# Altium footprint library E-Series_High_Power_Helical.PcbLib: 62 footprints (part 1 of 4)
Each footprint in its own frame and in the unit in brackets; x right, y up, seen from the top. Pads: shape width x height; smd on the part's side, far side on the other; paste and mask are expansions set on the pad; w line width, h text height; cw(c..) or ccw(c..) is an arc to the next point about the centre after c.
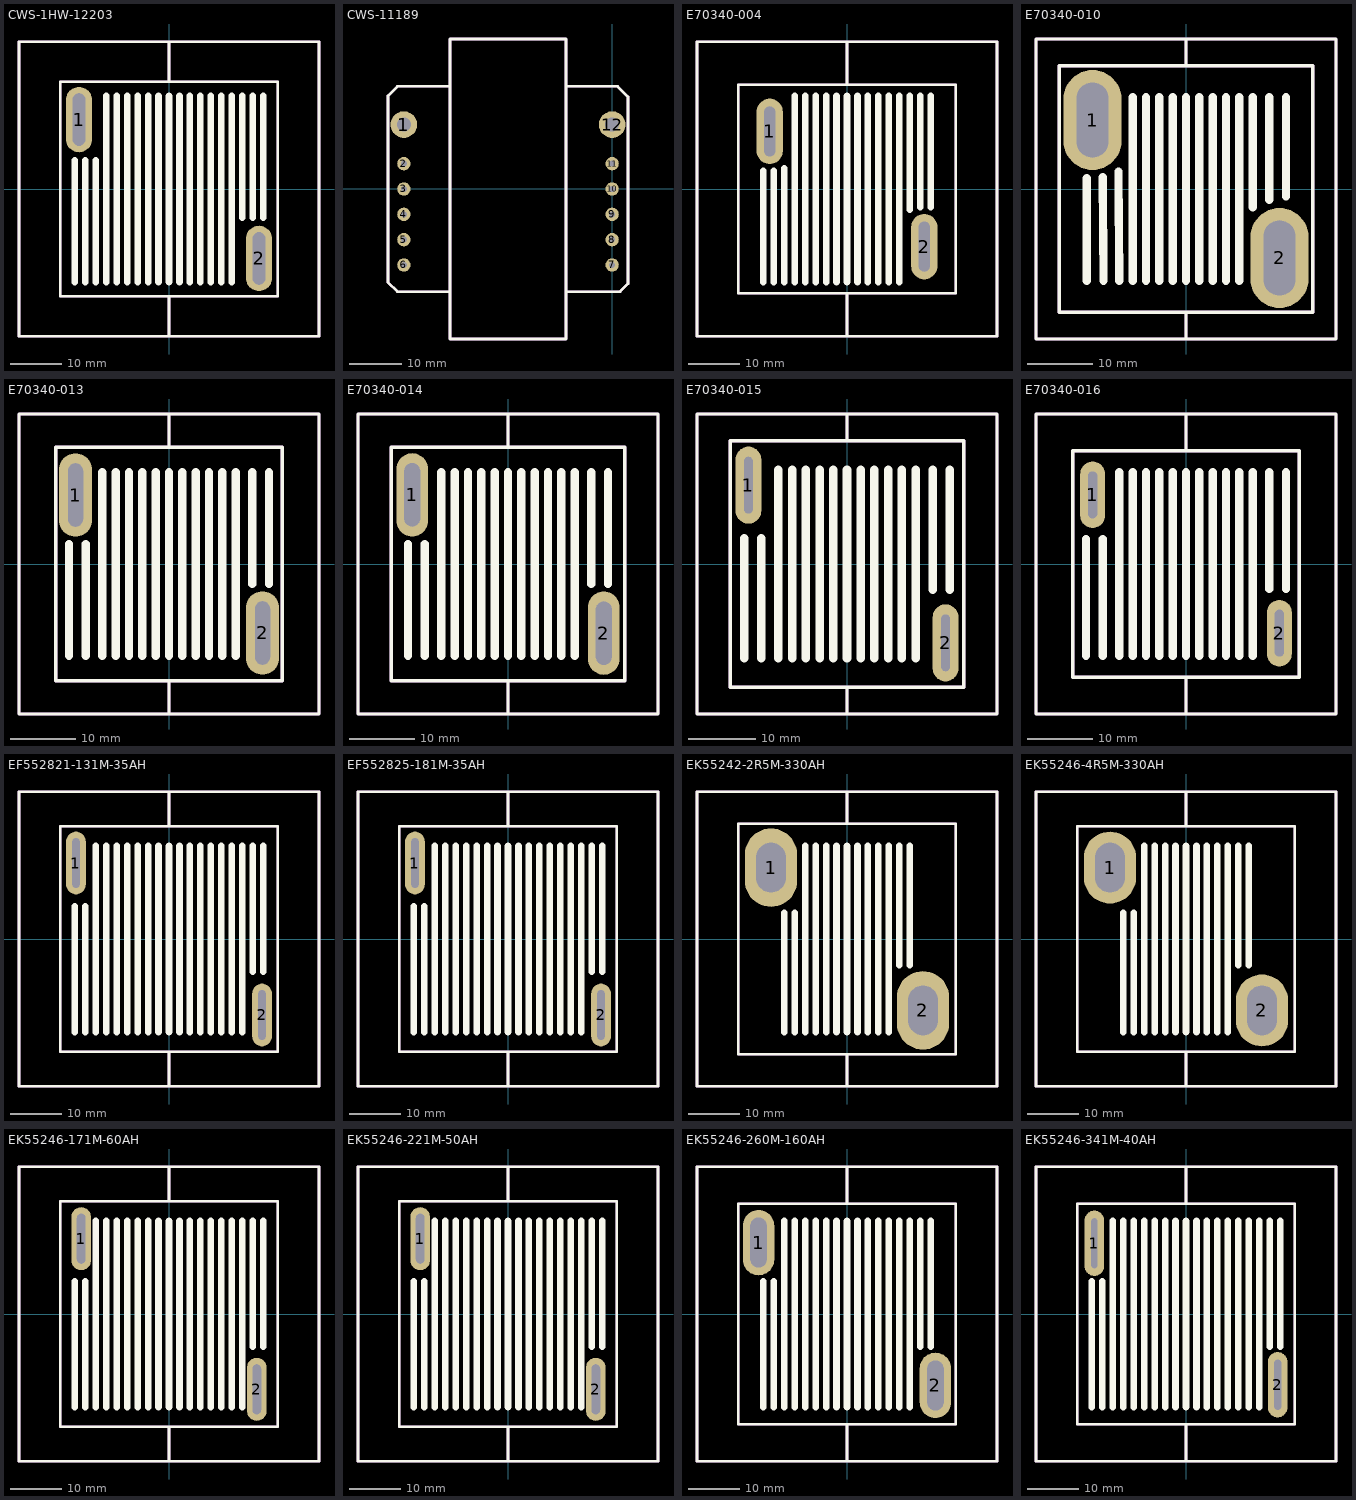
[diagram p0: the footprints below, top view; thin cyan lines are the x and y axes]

## CWS-1HW-12203 [mil]
pads (2):
  oval 200x500 hole 95 slot 400 at 90 deg: 1(-687,530) 2(687,-530)
Top Overlay:
  lines w19.68: 0,-1120 0,-820 ; 0,820 0,1120 ; -1145,-1125 -1145,1125 1145,1125 1145,-1125 -1145,-1125 ; -830,-820 -830,820 830,820 830,-820 -830,-820
  lines w50: -720,-710 -720,220 ; -640,-710 -640,220 ; -560,-710 -560,220 ; -480,-710 -480,710 ; -400,-710 -400,710 ; -320,-710 -320,710 ; -240,-710 -240,710 ; -160,-710 -160,710 ; -80,-710 -80,710 ; 0,-710 0,710 ; 80,-710 80,710 ; 160,-710 160,710 ; 240,-710 240,710 ; 320,-710 320,710 ; 400,-710 400,710 ; 480,-710 480,710 ; 560,-220 560,710 ; 640,-220 640,710 ; 720,-220 720,710
Components Top Assy:
  lines w19.68: 0,-1120 0,-820 ; 0,820 0,1120 ; -1145,-1125 -1145,1125 1145,1125 1145,-1125 -1145,-1125 ; -830,-820 -830,820 830,820 830,-820 -830,-820
  text "'.Designator'" at -938.15,-44.83 h400

## CWS-11189 [mil]
pads (12):
  round 200 hole 105: 1(-1562,483) 12(0,483)
  round 100 hole 45: 2(-1562,190) 3(-1562,0) 4(-1562,-190) 5(-1562,-380) 6(-1562,-570) 7(0,-570) 8(0,-380) 9(0,-190) 10(0,0) 11(0,190)
Top Overlay:
  lines w19.68: -1220,-770 -1607.04,-770 -1611.2,-770 -1681,-700.2 -1681,-690 -1681,669.63 -1681,699 -1610,770 -1580.42,770 -1220,770 ; -1216,1120 -1216,-1125 -346,-1125 -346,1120 ; -1216,1125 -346,1125 ; -340,-770 58.58,-770 119,-709.58 119,691 40,770 -340,770
Components Top Assy:
  lines w19.68: -1220,-770 -1607.04,-770 -1611.2,-770 -1681,-700.2 -1681,-690 -1681,669.63 -1681,699 -1610,770 -1580.42,770 -1220,770 ; -1216,1120 -1216,-1125 -346,-1125 -346,1120 ; -1216,1125 -346,1125 ; -340,-770 58.58,-770 119,-709.58 119,691 40,770 -340,770
  text "'.Designator'" at -1750,-64.83 h400

## E70340-004 [mil]
pads (2):
  oval 200x500 hole 85 slot 380 at 90 deg: 1(-590,440) 2(590,-440)
Top Overlay:
  lines w19.68: 0,-1120 0,-795 ; 0,800 0,1120 ; -1145,-1125 -1145,1125 1145,1125 1145,-1125 -1145,-1125 ; -830,-795 -830,795 830,795 830,-795 -830,-795
  lines w50: -640,-710 -640,140 ; -560,-710 -560,140 ; -480,-710 -480,160 ; -400,-710 -400,710 ; -320,-710 -320,710 ; -240,-710 -240,710 ; -160,-710 -160,710 ; -80,-710 -80,710 ; 0,-710 0,710 ; 80,-710 80,710 ; 160,-710 160,710 ; 240,-710 240,710 ; 320,-710 320,710 ; 400,-710 400,710 ; 480,-160 480,710 ; 560,-140 560,710 ; 640,-140 640,710
Components Top Assy:
  lines w19.68: 0,-1120 0,-795 ; 0,800 0,1120 ; -1145,-1125 -1145,1125 1145,1125 1145,-1125 -1145,-1125 ; -830,-795 -830,795 830,795 830,-795 -830,-795
  text "'.Designator'" at -938.15,-44.83 h400

## E70340-010 [mil]
pads (2):
  oval 350x600 hole 190 slot 450 at 90 deg: 1(-561,414) 2(561,-414)
Top Overlay:
  lines w19.68: 0,-890 0,-740 ; 0,740 0,895 ; -900,-900 900,-900 900,900 -900,900 -900,-900 ; -760,-740 760,-740 760,740 -760,740 -760,-740
  lines w50: -595,-550 -595,65 ; -500,70 -495,-550 ; -405,105 -400,-550 ; -320,-550 -320,550 ; -240,-550 -240,550 ; -160,-550 -160,550 ; -80,-550 -80,550 ; 0,-550 0,550 ; 80,-550 80,550 ; 160,-550 160,550 ; 240,-550 240,550 ; 320,-550 320,550 ; 400,-110 400,550 ; 500,-65 500,550 ; 600,-45 600,550
Components Top Assy:
  lines w19.68: 0,-890 0,-740 ; 0,740 0,895 ; -900,-900 900,-900 900,900 -900,900 -900,-900 ; -760,-740 760,-740 760,740 -760,740 -760,-740
  text "'.Designator'" at -928.15,-44.83 h400

## E70340-013 [mil]
pads (2):
  oval 200x500 hole 90 slot 380 at 90 deg: 1(-561,414) 2(561,-414)
Top Overlay:
  lines w19.68: 0,-890 0,-700 ; 0,700 0,895 ; -900,-900 -900,900 900,900 900,-900 -900,-900 ; -680,-700 -680,700 680,700 680,-700 -680,-700
  lines w50: -600,-550 -600,120 ; -500,-550 -500,120 ; -400,-550 -400,550 ; -320,-550 -320,550 ; -240,-550 -240,550 ; -160,-550 -160,550 ; -80,-550 -80,550 ; 0,-550 0,550 ; 80,-550 80,550 ; 160,-550 160,550 ; 240,-550 240,550 ; 320,-550 320,550 ; 400,-550 400,550 ; 500,-120 500,550 ; 600,-120 600,550
Components Top Assy:
  lines w19.68: 0,-890 0,-700 ; 0,700 0,895 ; -900,-900 -900,900 900,900 900,-900 -900,-900 ; -680,-700 -680,700 680,700 680,-700 -680,-700
  text "'.Designator'" at -928.15,-44.83 h400

## E70340-014 [mil]
pads (2):
  oval 190x500 hole 95 slot 380 at 90 deg: 1(-575,415) 2(575,-415)
Top Overlay:
  lines w19.68: 0,-890 0,-700 ; 0,700 0,895 ; -900,-900 -900,900 900,900 900,-900 -900,-900 ; -700,-700 -700,700 700,700 700,-700 -700,-700
  lines w50: -600,-550 -600,120 ; -500,-550 -500,120 ; -400,-550 -400,550 ; -320,-550 -320,550 ; -240,-550 -240,550 ; -160,-550 -160,550 ; -80,-550 -80,550 ; 0,-550 0,550 ; 80,-550 80,550 ; 160,-550 160,550 ; 240,-550 240,550 ; 320,-550 320,550 ; 400,-550 400,550 ; 500,-120 500,550 ; 600,-120 600,550
Components Top Assy:
  lines w19.68: 0,-890 0,-700 ; 0,700 0,895 ; -900,-900 -900,900 900,900 900,-900 -900,-900 ; -700,-700 -700,700 700,700 700,-700 -700,-700
  text "'.Designator'" at -928.15,-44.83 h400

## E70340-015 [mil]
pads (2):
  oval 150x450 hole 50 slot 330 at 90 deg: 1(-575,460) 2(575,-460)
Top Overlay:
  lines w19.68: -875,870 -875,-875 875,-875 875,870 ; -875,875 875,875 ; 0,-875 0,-720 ; 0,720 0,865 ; -680,-720 680,-720 680,720 -680,720 -680,-720
  lines w50: -600,-550 -600,150 ; -500,-550 -500,150 ; -400,-550 -400,550 ; -320,-550 -320,550 ; -240,-550 -240,550 ; -160,-550 -160,550 ; -80,-550 -80,550 ; 0,-550 0,550 ; 80,-550 80,550 ; 160,-550 160,550 ; 240,-550 240,550 ; 320,-550 320,550 ; 400,-550 400,550 ; 500,-150 500,550 ; 600,-150 600,550
Components Top Assy:
  lines w19.68: -875,870 -875,-875 875,-875 875,870 ; -875,875 875,875 ; 0,-875 0,-720 ; 0,720 0,865 ; -680,-720 680,-720 680,720 -680,720 -680,-720
  text "'.Designator'" at -938.15,-44.83 h400

## E70340-016 [mil]
pads (2):
  oval 150x400 hole 55 slot 280 at 90 deg: 1(-560,415) 2(560,-415)
Top Overlay:
  lines w19.68: 0,-890 0,-680 ; 0,680 0,895 ; -900,-900 -900,900 900,900 900,-900 -900,-900 ; -680,-680 -680,680 680,680 680,-680 -680,-680
  lines w50: -600,-550 -600,150 ; -500,-550 -500,150 ; -400,-550 -400,550 ; -320,-550 -320,550 ; -240,-550 -240,550 ; -160,-550 -160,550 ; -80,-550 -80,550 ; 0,-550 0,550 ; 80,-550 80,550 ; 160,-550 160,550 ; 240,-550 240,550 ; 320,-550 320,550 ; 400,-550 400,550 ; 500,-150 500,550 ; 600,-150 600,550
Components Top Assy:
  lines w19.68: 0,-890 0,-680 ; 0,680 0,895 ; -900,-900 -900,900 900,900 900,-900 -900,-900 ; -680,-680 -680,680 680,680 680,-680 -680,-680
  text "'.Designator'" at -928.15,-44.83 h400

## EF552821-131M-35AH [mil]
pads (2):
  oval 150x480 hole 55 slot 380 at 90 deg: 1(-710,580) 2(710,-580)
Top Overlay:
  lines w19.68: 0,-1120 0,-860 ; 0,860 0,1120 ; -1145,-1125 1145,-1125 1145,1125 -1145,1125 -1145,-1125 ; -830,-860 830,-860 830,860 -830,860 -830,-860
  lines w50: -720,-710 -720,250 ; -640,-710 -640,250 ; -560,-710 -560,710 ; -480,-710 -480,710 ; -400,-710 -400,710 ; -320,-710 -320,710 ; -240,-710 -240,710 ; -160,-710 -160,710 ; -80,-710 -80,710 ; 0,-710 0,710 ; 80,-710 80,710 ; 160,-710 160,710 ; 240,-710 240,710 ; 320,-710 320,710 ; 400,-710 400,710 ; 480,-710 480,710 ; 560,-710 560,710 ; 640,-250 640,710 ; 720,-250 720,710
Components Top Assy:
  lines w19.68: 0,-1120 0,-860 ; 0,860 0,1120 ; -1145,-1125 1145,-1125 1145,1125 -1145,1125 -1145,-1125 ; -830,-860 830,-860 830,860 -830,860 -830,-860
  text "'.Designator'" at -938.15,-44.83 h400

## EF552825-181M-35AH [mil]
pads (2):
  oval 150x480 hole 55 slot 380 at 90 deg: 1(-710,580) 2(710,-580)
Top Overlay:
  lines w19.68: 0,-1120 0,-860 ; 0,860 0,1120 ; -1145,-1125 1145,-1125 1145,1125 -1145,1125 -1145,-1125 ; -830,-860 830,-860 830,860 -830,860 -830,-860
  lines w50: -720,-710 -720,250 ; -640,-710 -640,250 ; -560,-710 -560,710 ; -480,-710 -480,710 ; -400,-710 -400,710 ; -320,-710 -320,710 ; -240,-710 -240,710 ; -160,-710 -160,710 ; -80,-710 -80,710 ; 0,-710 0,710 ; 80,-710 80,710 ; 160,-710 160,710 ; 240,-710 240,710 ; 320,-710 320,710 ; 400,-710 400,710 ; 480,-710 480,710 ; 560,-710 560,710 ; 640,-250 640,710 ; 720,-250 720,710
Components Top Assy:
  lines w19.68: 0,-1120 0,-860 ; 0,860 0,1120 ; -1145,-1125 1145,-1125 1145,1125 -1145,1125 -1145,-1125 ; -830,-860 830,-860 830,860 -830,860 -830,-860
  text "'.Designator'" at -938.15,-44.83 h400

## EK55242-2R5M-330AH [mil]
pads (2):
  oval 400x600 hole 225 slot 380 at 90 deg: 1(-580,545) 2(580,-545)
Top Overlay:
  lines w19.68: 0,-1120 0,-880 ; 0,880 0,1120 ; -1145,-1125 1145,-1125 1145,1125 -1145,1125 -1145,-1125 ; -830,-880 830,-880 830,880 -830,880 -830,-880
  lines w50: -480,-710 -480,200 ; -400,-710 -400,200 ; -320,-710 -320,710 ; -240,-710 -240,710 ; -160,-710 -160,710 ; -80,-710 -80,710 ; 0,-710 0,710 ; 80,-710 80,710 ; 160,-710 160,710 ; 240,-710 240,710 ; 320,-710 320,710 ; 400,-200 400,710 ; 480,-200 480,710
Components Top Assy:
  lines w19.68: 0,-1120 0,-880 ; 0,880 0,1120 ; -1145,-1125 1145,-1125 1145,1125 -1145,1125 -1145,-1125 ; -830,-880 830,-880 830,880 -830,880 -830,-880
  text "'.Designator'" at -938.15,-44.83 h400

## EK55246-4R5M-330AH [mil]
pads (2):
  oval 400x550 hole 225 slot 380 at 90 deg: 1(-580,545) 2(580,-545)
Top Overlay:
  lines w19.68: 0,-1120 0,-860 ; 0,860 0,1120 ; -1145,-1125 1145,-1125 1145,1125 -1145,1125 -1145,-1125 ; -830,-860 830,-860 830,860 -830,860 -830,-860
  lines w50: -480,-710 -480,200 ; -400,-710 -400,200 ; -320,-710 -320,710 ; -240,-710 -240,710 ; -160,-710 -160,710 ; -80,-710 -80,710 ; 0,-710 0,710 ; 80,-710 80,710 ; 160,-710 160,710 ; 240,-710 240,710 ; 320,-710 320,710 ; 400,-200 400,710 ; 480,-200 480,710
Components Top Assy:
  lines w19.68: 0,-1120 0,-860 ; 0,860 0,1120 ; -1145,-1125 1145,-1125 1145,1125 -1145,1125 -1145,-1125 ; -830,-860 830,-860 830,860 -830,860 -830,-860
  text "'.Designator'" at -938.15,-44.83 h400

## EK55246-171M-60AH [mil]
pads (2):
  oval 150x480 hole 65 slot 380 at 90 deg: 1(-670,575) 2(670,-575)
Top Overlay:
  lines w19.68: 0,-1120 0,-860 ; 0,860 0,1120 ; -1145,-1125 -1145,1125 1145,1125 1145,-1125 -1145,-1125 ; -830,-860 -830,860 830,860 830,-860 -830,-860
  lines w50: -720,-710 -720,250 ; -640,-710 -640,250 ; -560,-710 -560,710 ; -480,-710 -480,710 ; -400,-710 -400,710 ; -320,-710 -320,710 ; -240,-710 -240,710 ; -160,-710 -160,710 ; -80,-710 -80,710 ; 0,-710 0,710 ; 80,-710 80,710 ; 160,-710 160,710 ; 240,-710 240,710 ; 320,-710 320,710 ; 400,-710 400,710 ; 480,-710 480,710 ; 560,-710 560,710 ; 640,-250 640,710 ; 720,-250 720,710
Components Top Assy:
  lines w19.68: 0,-1120 0,-860 ; 0,860 0,1120 ; -1145,-1125 1145,-1125 1145,1125 -1145,1125 -1145,-1125 ; -830,-860 830,-860 830,860 -830,860 -830,-860
  text "'.Designator'" at -938.15,-44.83 h400

## EK55246-221M-50AH [mil]
pads (2):
  oval 150x480 hole 65 slot 380 at 90 deg: 1(-670,575) 2(670,-575)
Top Overlay:
  lines w19.68: 0,-1120 0,-860 ; 0,860 0,1120 ; -1145,-1125 1145,-1125 1145,1125 -1145,1125 -1145,-1125 ; -830,-860 830,-860 830,860 -830,860 -830,-860
  lines w50: -720,-710 -720,250 ; -640,-710 -640,250 ; -560,-710 -560,710 ; -480,-710 -480,710 ; -400,-710 -400,710 ; -320,-710 -320,710 ; -240,-710 -240,710 ; -160,-710 -160,710 ; -80,-710 -80,710 ; 0,-710 0,710 ; 80,-710 80,710 ; 160,-710 160,710 ; 240,-710 240,710 ; 320,-710 320,710 ; 400,-710 400,710 ; 480,-710 480,710 ; 560,-710 560,710 ; 640,-250 640,710 ; 720,-250 720,710
Components Top Assy:
  lines w19.68: 0,-1120 0,-860 ; 0,860 0,1120 ; -1145,-1125 1145,-1125 1145,1125 -1145,1125 -1145,-1125 ; -830,-860 830,-860 830,860 -830,860 -830,-860
  text "'.Designator'" at -938.15,-44.83 h400

## EK55246-260M-160AH [mil]
pads (2):
  oval 240x500 hole 125 slot 380 at 90 deg: 1(-675,545) 2(675,-545)
Top Overlay:
  lines w19.68: 0,-1120 0,-840 ; 0,840 0,1120 ; -1145,-1125 1145,-1125 1145,1125 -1145,1125 -1145,-1125 ; -830,-840 830,-840 830,840 -830,840 -830,-840
  lines w50: -640,-710 -640,250 ; -560,-710 -560,250 ; -480,-710 -480,710 ; -400,-710 -400,710 ; -320,-710 -320,710 ; -240,-710 -240,710 ; -160,-710 -160,710 ; -80,-710 -80,710 ; 0,-710 0,710 ; 80,-710 80,710 ; 160,-710 160,710 ; 240,-710 240,710 ; 320,-710 320,710 ; 400,-710 400,710 ; 480,-710 480,710 ; 560,-250 560,710 ; 640,-250 640,710
Components Top Assy:
  lines w19.68: 0,-1120 0,-840 ; 0,840 0,1120 ; -1145,-1125 -1145,1125 1145,1125 1145,-1125 -1145,-1125 ; -830,-840 -830,840 830,840 830,-840 -830,-840
  text "'.Designator'" at -938.15,-44.83 h400

## EK55246-341M-40AH [mil]
pads (2):
  oval 150x500 hole 45 slot 380 at 90 deg: 1(-700,540)
  oval 150x500 hole 55 slot 380 at 90 deg: 2(700,-540)
Top Overlay:
  lines w19.68: 0,-1120 0,-840 ; 0,840 0,1120 ; -1145,-1125 -1145,1125 1145,1125 1145,-1125 -1145,-1125 ; -830,-840 -830,840 830,840 830,-840 -830,-840
  lines w50: -720,-710 -720,250 ; -640,-710 -640,250 ; -560,-710 -560,710 ; -480,-710 -480,710 ; -400,-710 -400,710 ; -320,-710 -320,710 ; -240,-710 -240,710 ; -160,-710 -160,710 ; -80,-710 -80,710 ; 0,-710 0,710 ; 80,-710 80,710 ; 160,-710 160,710 ; 240,-710 240,710 ; 320,-710 320,710 ; 400,-710 400,710 ; 480,-710 480,710 ; 560,-710 560,710 ; 640,-250 640,710 ; 720,-250 720,710
Components Top Assy:
  lines w19.68: 0,-1120 0,-840 ; 0,840 0,1120 ; -1145,-1125 -1145,1125 1145,1125 1145,-1125 -1145,-1125 ; -830,-840 -830,840 830,840 830,-840 -830,-840
  text "'.Designator'" at -938.15,-44.83 h400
